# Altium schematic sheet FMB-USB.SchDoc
size A4
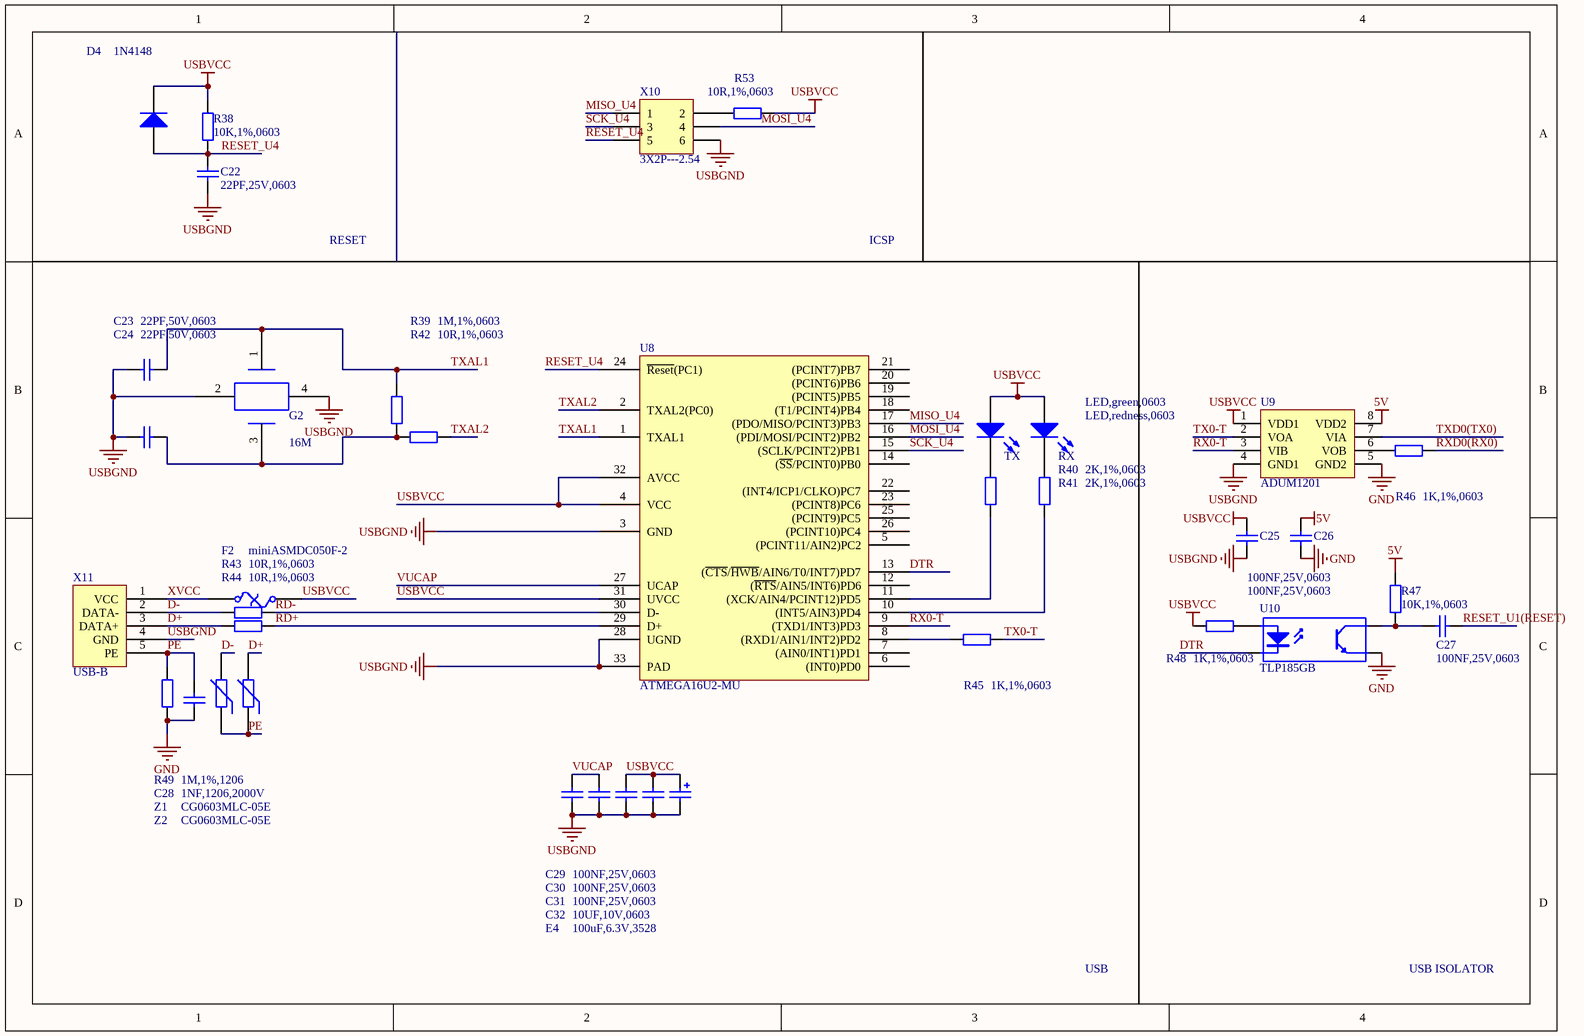
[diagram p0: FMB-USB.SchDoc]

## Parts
C22  22PF,25V,0603  [RC0603]
C23  22PF,50V,0603  [RC0603]
C24  22PF,50V,0603  [RC0603]
C25  100NF,25V,0603  [RC0603]
C26  100NF,25V,0603  [RC0603]
C27  100NF,25V,0603  [RC0603]
C28  1NF,1206,2000V  [RC1206]
C29  100NF,25V,0603  [RC0603]
C30  100NF,25V,0603  [RC0603]
C31  100NF,25V,0603  [RC0603]
C32  10UF,10V,0603  [RC0603]
D4  1N4148  [SOD-323]
E4  100uF,6.3V,3528  [3528-21]
F2  miniASMDC050F-2  [RC1812]
G2  16M  [Y-3225]
R38  10K,1%,0603  [RC0603]
R39  1M,1%,0603  [RC0603]
R40  2K,1%,0603  [RC0603]
R41  2K,1%,0603  [RC0603]
R42  10R,1%,0603  [RC0603]
R43  10R,1%,0603  [RC0603]
R44  10R,1%,0603  [RC0603]
R45  1K,1%,0603  [RC0603]
R46  1K,1%,0603  [RC0603]
R47  10K,1%,0603  [RC0603]
R48  1K,1%,0603  [RC0603]
R49  1M,1%,1206  [RC1206]
R53  10R,1%,0603  [RC0603]
RX  LED,redness,0603  [LED-0603]
TX  LED,green,0603  [LED-0603]
U8  ATMEGA16U2-MU  [QFN-32]
U9  ADUM1201  [SO-8N]
U10  TLP185GB  [SO-4]
X10  3X2P---2.54  [HDR2X3]
X11  USB-B  [USB-B180]
Z1  CG0603MLC-05E  [RC0603]
Z2  CG0603MLC-05E  [RC0603]

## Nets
5V: C26.1 R47.2 U9.8(VDD2)
GND: C26.2 C28.1 R49.1 U9.5(GND2) U10.3(E)
USBGND: C22.2 C23.2 C24.2 C25.1 C29.1 C30.1 C31.1 C32.1 E4.2 G2.2 G2.4 U8.3(GND) U8.28(UGND) U8.33(PAD) U9.4(GND1) X10.6 X11.4(GND)
USBVCC: C25.2 C31.2 C32.2 D4.2(K) E4.1 F2.2 R38.1 R48.1 R53.1 RX.1(A) TX.1(A) U8.4(VCC) U8.31(UVCC) U8.32(AVCC) U9.1(VDD1)
D+: R44.1 X11.3(DATA+) Z2.2
D-: R43.1 X11.2(DATA-) Z1.2
DTR: U8.13((~{CTS}/~{HWB}/AIN6/T0/INT7)PD7) U10.2(K)
MISO_U4: U8.17((PDO/MISO/PCINT3)PB3) X10.1
MOSI_U4: U8.16((PDI/MOSI/PCINT2)PB2) X10.4
PE: C28.2 R49.2 X11.5(PE) Z1.1 Z2.1
RD+: R44.2 U8.29(D+)
RD-: R43.2 U8.30(D-)
RESET_U1(RESET): C27.1
RESET_U4: C22.1 D4.1(A) R38.2 U8.24(~{Reset}(PC1)) X10.5
RX0-T: U8.9((TXD1/INT3)PD3) U9.3(VIB)
RXD0(RX0): R46.1
SCK_U4: U8.15((SCLK/PCINT2)PB1) X10.3
TX0-T: R45.1 U9.2(VOA)
TXAL1: C23.1 G2.1 R39.1 U8.1(TXAL1)
TXAL2: R42.2 U8.2(TXAL2(PC0))
TXD0(TX0): U9.7(VIA)
VUCAP: C29.2 C30.2 U8.27(UCAP)
XVCC: F2.1 X11.1(VCC)
NetC24_1: C24.1 G2.3 R39.2 R42.1
NetC27_2: C27.2 R47.1 U10.4(C)
NetR40_1: R40.1 TX.2(K)
NetR40_2: R40.2 U8.11((XCK/AIN4/PCINT12)PD5)
NetR41_1: R41.1 RX.2(K)
NetR41_2: R41.2 U8.10((INT5/AIN3)PD4)
NetR45_2: R45.2 U8.8((RXD1/AIN1/INT2)PD2)
NetR46_2: R46.2 U9.6(VOB)
NetR48_2: R48.2 U10.1(A)
NetR53_2: R53.2 X10.2

Not connected (* = marked no-connect by the designer): U8 5((PCINT11/AIN2)PC2) 6((INT0)PD0) 7((AIN0/INT1)PD1) 12((~{RTS}/AIN5/INT6)PD6) 14((~{SS}/PCINT0)PB0) 18((T1/PCINT4)PB4) 19((PCINT5)PB5) 20((PCINT6)PB6) 21((PCINT7)PB7) 22((INT4/ICP1/CLKO)PC7) 23((PCINT8)PC6) 25((PCINT9)PC5) 26((PCINT10)PC4)

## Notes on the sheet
- RESET
- ICSP
- USB
- USB ISOLATOR

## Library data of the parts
C22-C32 = Cap: Capacitor; Value: 100pF
D4 = Diode: Default Diode
E4 = Cap Pol2: Polarized Capacitor (Axial)
F2 = Fuse Thermal: Thermal Fuse
G2 = G
R38-R44 R47 R49 R53 = Res2: Resistor; Value: 1K
R45 R46 R48 = Res2: Resistor
RX TX = LED0: Typical INFRARED GaAs LED
U8 = ATMEGA8U2-MU
U10 = Optoisolator1: 4-Pin Phototransistor Optocoupler
X10 = Header 3X2: Header, 3-Pin, Dual row
X11 = B-USC
Z1 Z2 = Res Varistor: Varistor (Voltage-Sensitive Resistor)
